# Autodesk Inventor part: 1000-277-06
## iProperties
Created: 2012-08
Part Number: 1000-277-06
Document SubType Name: Modeling
Designer: Administrator
Density: 7.85 g/cm^3
Material: Steel
Mass: 9.05307 g
Surface Area: 10.5198 cm^2
Volume: 1.15326 cm^3
Author: Administrator
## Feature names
1. Base1
